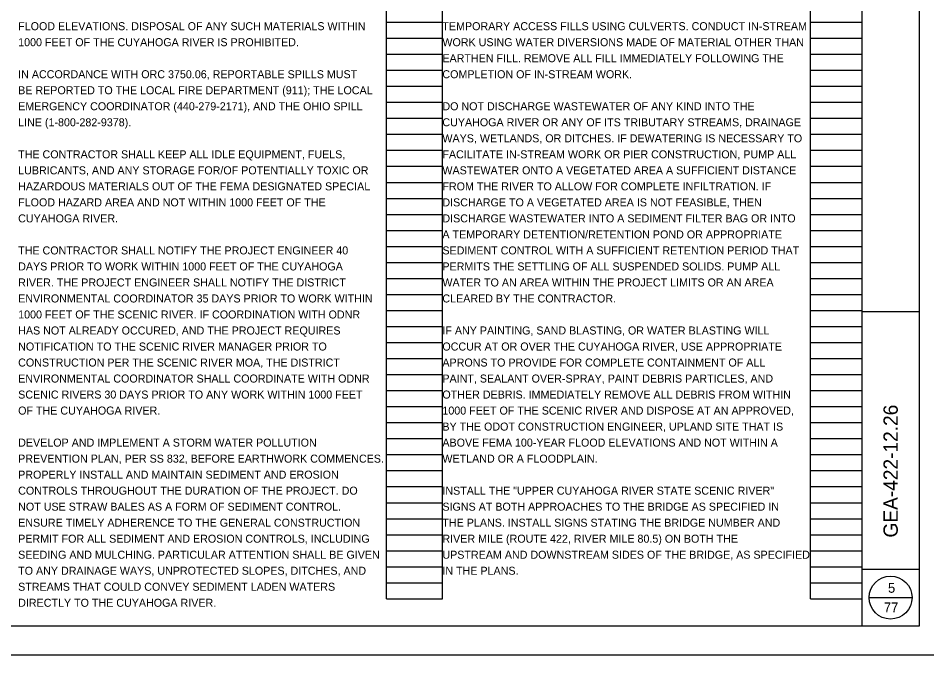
# Model space of a CAD drawing. Extents: x -6.4 to 41.8, y 0 to 22.
# Drawn here: x 17.74 to 33.63, y 0 to 11.13 of the extents above; entities that cross this region are included whole.
import ezdxf

# ---------------------------------------------------------------- set-up
doc = ezdxf.new("R2010")
doc.units = 0
for name, color, linetype in [('SC_Scratch1', 7, 'Continuous'), ('SH_Border', 7, 'Continuous'), ('SH_Cut_Line', 7, 'Continuous'), ('SH_Data', 7, 'Continuous'), ('SH_Text', 7, 'Continuous')]:
    doc.layers.add(name, color=color, linetype=linetype)

msp = doc.modelspace()

# ---------------------------------------------------------------- linework, layer by layer
at = {"layer": 'SC_Scratch1'}
for p, q in [((24.18, 0.98), (24.18, 21.14)), ((25.16, 0.98), (25.16, 21.14)), ((31.6, 0.98), (31.6, 21.14)), ((32.5, 0.98), (32.5, 21.14)), ((24.18, 11.06), (25.16, 11.06)), ((31.6, 11.06), (32.5, 11.06)), ((24.18, 10.78), (25.16, 10.78)), ((31.6, 10.78), (32.5, 10.78)), ((24.18, 10.5), (25.16, 10.5)), ((31.6, 10.5), (32.5, 10.5)), ((24.18, 10.22), (25.16, 10.22)), ((31.6, 10.22), (32.5, 10.22)), ((24.18, 9.94), (25.16, 9.94)), ((31.6, 9.94), (32.5, 9.94)), ((24.18, 9.66), (25.16, 9.66)), ((31.6, 9.66), (32.5, 9.66)), ((24.18, 9.38), (25.16, 9.38)), ((31.6, 9.38), (32.5, 9.38)), ((24.18, 9.1), (25.16, 9.1)), ((31.6, 9.1), (32.5, 9.1)), ((24.18, 8.82), (25.16, 8.82)), ((31.6, 8.82), (32.5, 8.82)), ((24.18, 8.54), (25.16, 8.54)), ((31.6, 8.54), (32.5, 8.54)), ((24.18, 8.26), (25.16, 8.26)), ((31.6, 8.26), (32.5, 8.26)), ((24.18, 7.98), (25.16, 7.98)), ((31.6, 7.98), (32.5, 7.98)), ((24.18, 7.7), (25.16, 7.7)), ((31.6, 7.7), (32.5, 7.7)), ((24.18, 7.42), (25.16, 7.42)), ((31.6, 7.42), (32.5, 7.42)), ((24.18, 7.14), (25.16, 7.14)), ((31.6, 7.14), (32.5, 7.14)), ((24.18, 6.86), (25.16, 6.86)), ((31.6, 6.86), (32.5, 6.86)), ((24.18, 6.58), (25.16, 6.58)), ((31.6, 6.58), (32.5, 6.58)), ((24.18, 6.3), (25.16, 6.3)), ((31.6, 6.3), (32.5, 6.3)), ((24.18, 6.02), (25.16, 6.02)), ((31.6, 6.02), (32.5, 6.02)), ((24.18, 5.74), (25.16, 5.74)), ((31.6, 5.74), (32.5, 5.74)), ((24.18, 5.46), (25.16, 5.46)), ((31.6, 5.46), (32.5, 5.46)), ((24.18, 5.18), (25.16, 5.18)), ((31.6, 5.18), (32.5, 5.18)), ((24.18, 4.9), (25.16, 4.9)), ((31.6, 4.9), (32.5, 4.9)), ((24.18, 4.62), (25.16, 4.62)), ((31.6, 4.62), (32.5, 4.62)), ((24.18, 4.34), (25.16, 4.34)), ((31.6, 4.34), (32.5, 4.34)), ((24.18, 4.06), (25.16, 4.06)), ((31.6, 4.06), (32.5, 4.06)), ((24.18, 3.78), (25.16, 3.78)), ((31.6, 3.78), (32.5, 3.78)), ((24.18, 3.5), (25.16, 3.5)), ((31.6, 3.5), (32.5, 3.5)), ((24.18, 3.22), (25.16, 3.22)), ((31.6, 3.22), (32.5, 3.22)), ((24.18, 2.94), (25.16, 2.94)), ((31.6, 2.94), (32.5, 2.94)), ((24.18, 2.66), (25.16, 2.66)), ((31.6, 2.66), (32.5, 2.66)), ((24.18, 2.38), (25.16, 2.38)), ((31.6, 2.38), (32.5, 2.38)), ((24.18, 2.1), (25.16, 2.1)), ((31.6, 2.1), (32.5, 2.1)), ((24.18, 1.82), (25.16, 1.82)), ((31.6, 1.82), (32.5, 1.82)), ((24.18, 1.54), (25.16, 1.54)), ((31.6, 1.54), (32.5, 1.54)), ((24.18, 1.26), (25.16, 1.26)), ((31.6, 1.26), (32.5, 1.26)), ((24.18, 0.98), (25.16, 0.98)), ((31.6, 0.98), (32.5, 0.98))]:
    msp.add_line(p, q, dxfattribs=at)
at = {"layer": 'SH_Border'}
for p, q in [((32.5, 0.5), (32.5, 21.5)), ((32.5, 6), (33.5, 6)), ((32.5, 1.5), (33.5, 1.5))]:
    msp.add_line(p, q, dxfattribs=at)
msp.add_lwpolyline([(2, 21.5), (33.5, 21.5), (33.5, 0.5), (2, 0.5)], close=True, dxfattribs=at)
at = {"layer": 'SH_Cut_Line'}
msp.add_lwpolyline([(0, 0), (34, 0), (34, 22), (0, 22)], close=True, dxfattribs=at)
at = {"layer": 'SH_Data'}
msp.add_line((32.625, 1), (33.375, 1), dxfattribs=at)
msp.add_circle((33, 1), 0.375, dxfattribs=at)

# ---------------------------------------------------------------- texts
msp.add_text(' GEA-422-12.26 ', height=0.25, rotation=90, dxfattribs=at).set_placement((33.125, 1.957))
for s, p in [('5', (32.954, 1.085)), ('77', (32.882, 0.745))]:
    msp.add_text(s, height=0.17, dxfattribs=at).set_placement(p)
at = {"layer": 'SH_Text'}
for s, p in [('FLOOD ELEVATIONS. DISPOSAL OF ANY SUCH MATERIALS WITHIN ', (17.74, 10.92)), ('TEMPORARY ACCESS FILLS USING CULVERTS. CONDUCT IN-STREAM ', (25.16, 10.92)), ('1000 FEET OF THE CUYAHOGA RIVER IS PROHIBITED. ', (17.74, 10.64)), ('WORK USING WATER DIVERSIONS MADE OF MATERIAL OTHER THAN ', (25.16, 10.64)), ('EARTHEN FILL. REMOVE ALL FILL IMMEDIATELY FOLLOWING THE ', (25.16, 10.36)), ('IN ACCORDANCE WITH ORC 3750.06, REPORTABLE SPILLS MUST ', (17.74, 10.08)), ('COMPLETION OF IN-STREAM WORK. ', (25.16, 10.08)), ('BE REPORTED TO THE LOCAL FIRE DEPARTMENT (911); THE LOCAL ', (17.74, 9.8)), ('EMERGENCY COORDINATOR (440-279-2171), AND THE OHIO SPILL ', (17.74, 9.52)), ('DO NOT DISCHARGE WASTEWATER OF ANY KIND INTO THE ', (25.16, 9.52)), ('LINE (1-800-282-9378). ', (17.74, 9.24)), ('CUYAHOGA RIVER OR ANY OF ITS TRIBUTARY STREAMS, DRAINAGE ', (25.16, 9.24)), ('WAYS, WETLANDS, OR DITCHES. IF DEWATERING IS NECESSARY TO ', (25.16, 8.96)), ('THE CONTRACTOR SHALL KEEP ALL IDLE EQUIPMENT, FUELS, ', (17.74, 8.68)), ('FACILITATE IN-STREAM WORK OR PIER CONSTRUCTION, PUMP ALL ', (25.16, 8.68)), ('LUBRICANTS, AND ANY STORAGE FOR/OF POTENTIALLY TOXIC OR ', (17.74, 8.4)), ('WASTEWATER ONTO A VEGETATED AREA A SUFFICIENT DISTANCE ', (25.16, 8.4)), ('HAZARDOUS MATERIALS OUT OF THE FEMA DESIGNATED SPECIAL ', (17.74, 8.12)), ('FROM THE RIVER TO ALLOW FOR COMPLETE INFILTRATION. IF ', (25.16, 8.12)), ('FLOOD HAZARD AREA AND NOT WITHIN 1000 FEET OF THE ', (17.74, 7.84)), ('DISCHARGE TO A VEGETATED AREA IS NOT FEASIBLE, THEN ', (25.16, 7.84)), ('CUYAHOGA RIVER. ', (17.74, 7.56)), ('DISCHARGE WASTEWATER INTO A SEDIMENT FILTER BAG OR INTO ', (25.16, 7.56)), ('A TEMPORARY DETENTION/RETENTION POND OR APPROPRIATE ', (25.16, 7.28)), ('THE CONTRACTOR SHALL NOTIFY THE PROJECT ENGINEER 40 ', (17.74, 7)), ('SEDIMENT CONTROL WITH A SUFFICIENT RETENTION PERIOD THAT ', (25.16, 7)), ('DAYS PRIOR TO WORK WITHIN 1000 FEET OF THE CUYAHOGA ', (17.74, 6.72)), ('PERMITS THE SETTLING OF ALL SUSPENDED SOLIDS. PUMP ALL ', (25.16, 6.72)), ('RIVER. THE PROJECT ENGINEER SHALL NOTIFY THE DISTRICT ', (17.74, 6.44)), ('WATER TO AN AREA WITHIN THE PROJECT LIMITS OR AN AREA ', (25.16, 6.44)), ('ENVIRONMENTAL COORDINATOR 35 DAYS PRIOR TO WORK WITHIN ', (17.74, 6.16)), ('CLEARED BY THE CONTRACTOR. ', (25.16, 6.16)), ('1000 FEET OF THE SCENIC RIVER. IF COORDINATION WITH ODNR ', (17.74, 5.88)), ('HAS NOT ALREADY OCCURED, AND THE PROJECT REQUIRES ', (17.74, 5.6)), ('IF ANY PAINTING, SAND BLASTING, OR WATER BLASTING WILL ', (25.16, 5.6)), ('NOTIFICATION TO THE SCENIC RIVER MANAGER PRIOR TO ', (17.74, 5.32)), ('OCCUR AT OR OVER THE CUYAHOGA RIVER, USE APPROPRIATE ', (25.16, 5.32)), ('CONSTRUCTION PER THE SCENIC RIVER MOA, THE DISTRICT ', (17.74, 5.04)), ('APRONS TO PROVIDE FOR COMPLETE CONTAINMENT OF ALL ', (25.16, 5.04)), ('ENVIRONMENTAL COORDINATOR SHALL COORDINATE WITH ODNR ', (17.74, 4.76)), ('PAINT, SEALANT OVER-SPRAY, PAINT DEBRIS PARTICLES, AND ', (25.16, 4.76)), ('SCENIC RIVERS 30 DAYS PRIOR TO ANY WORK WITHIN 1000 FEET ', (17.74, 4.48)), ('OTHER DEBRIS. IMMEDIATELY REMOVE ALL DEBRIS FROM WITHIN ', (25.16, 4.48)), ('OF THE CUYAHOGA RIVER. ', (17.74, 4.2)), ('1000 FEET OF THE SCENIC RIVER AND DISPOSE AT AN APPROVED, ', (25.16, 4.2)), ('BY THE ODOT CONSTRUCTION ENGINEER, UPLAND SITE THAT IS ', (25.16, 3.92)), ('DEVELOP AND IMPLEMENT A STORM WATER POLLUTION ', (17.74, 3.64)), ('ABOVE FEMA 100-YEAR FLOOD ELEVATIONS AND NOT WITHIN A ', (25.16, 3.64)), ('PREVENTION PLAN, PER SS 832, BEFORE EARTHWORK COMMENCES. ', (17.74, 3.36)), ('WETLAND OR A FLOODPLAIN. ', (25.16, 3.36)), ('PROPERLY INSTALL AND MAINTAIN SEDIMENT AND EROSION ', (17.74, 3.08)), ('CONTROLS THROUGHOUT THE DURATION OF THE PROJECT. DO ', (17.74, 2.8)), ('INSTALL THE "UPPER CUYAHOGA RIVER STATE SCENIC RIVER" ', (25.16, 2.8)), ('NOT USE STRAW BALES AS A FORM OF SEDIMENT CONTROL. ', (17.74, 2.52)), ('SIGNS AT BOTH APPROACHES TO THE BRIDGE AS SPECIFIED IN ', (25.16, 2.52)), ('ENSURE TIMELY ADHERENCE TO THE GENERAL CONSTRUCTION ', (17.74, 2.24)), ('THE PLANS. INSTALL SIGNS STATING THE BRIDGE NUMBER AND ', (25.16, 2.24)), ('PERMIT FOR ALL SEDIMENT AND EROSION CONTROLS, INCLUDING ', (17.74, 1.96)), ('RIVER MILE (ROUTE 422, RIVER MILE 80.5) ON BOTH THE ', (25.16, 1.96)), ('SEEDING AND MULCHING. PARTICULAR ATTENTION SHALL BE GIVEN ', (17.74, 1.68)), ('UPSTREAM AND DOWNSTREAM SIDES OF THE BRIDGE, AS SPECIFIED ', (25.16, 1.68)), ('TO ANY DRAINAGE WAYS, UNPROTECTED SLOPES, DITCHES, AND ', (17.74, 1.4)), ('IN THE PLANS. ', (25.16, 1.4)), ('STREAMS THAT COULD CONVEY SEDIMENT LADEN WATERS ', (17.74, 1.12)), ('DIRECTLY TO THE CUYAHOGA RIVER. ', (17.74, 0.84))]:
    msp.add_text(s, height=0.14, dxfattribs=at).set_placement(p)

doc.saveas('drawing.dxf')
